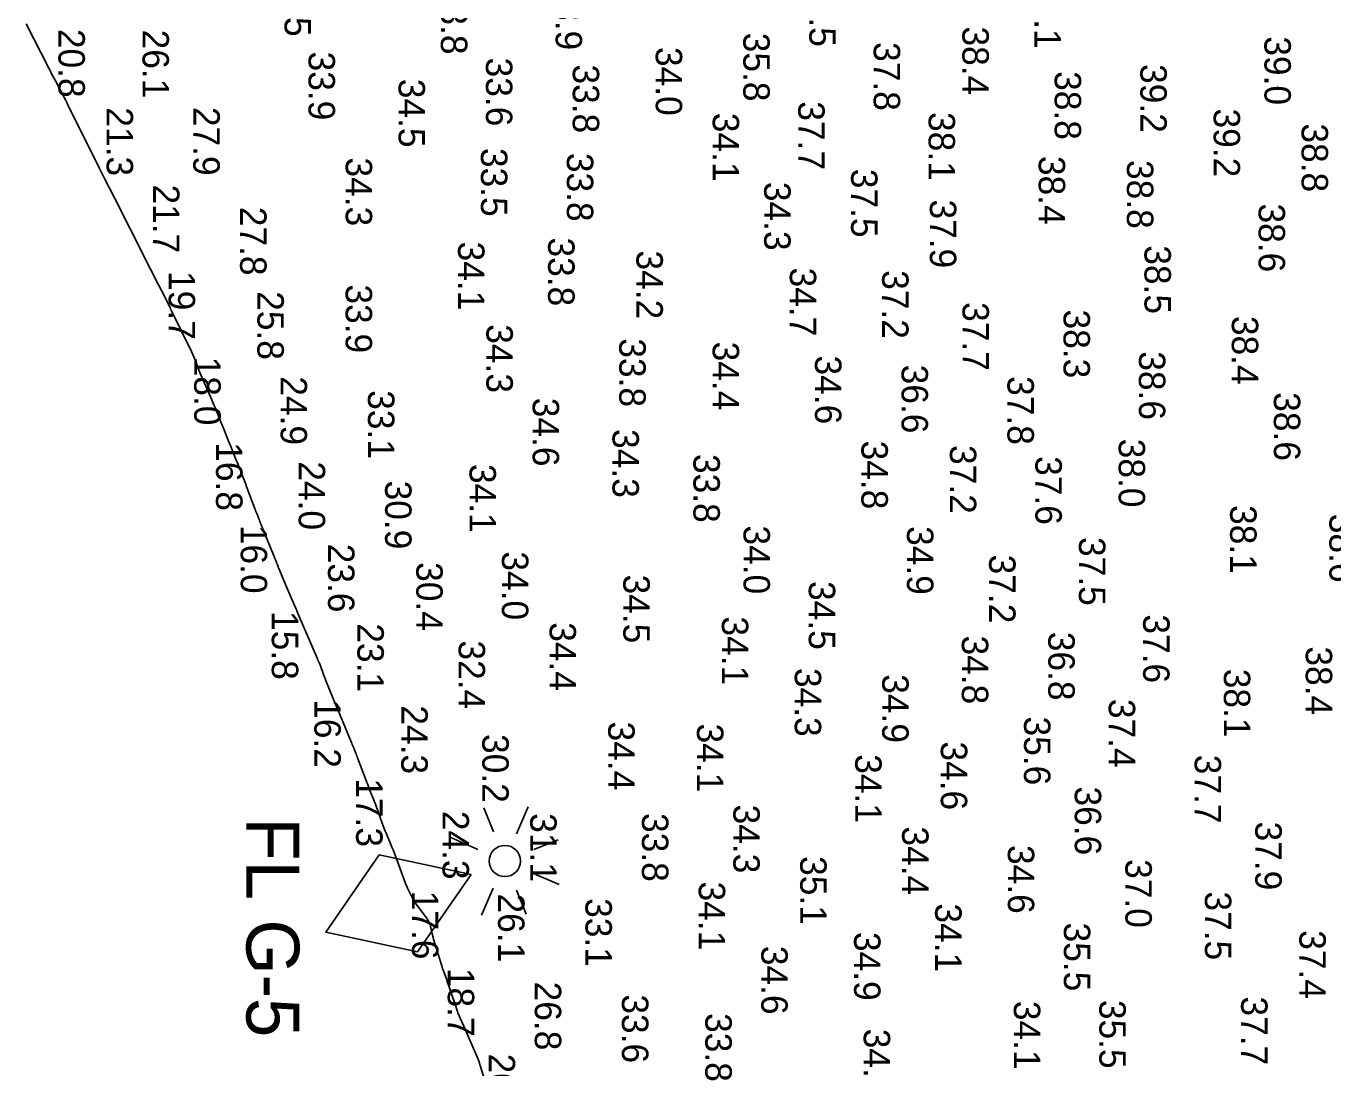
# Model space of a CAD drawing. Extents: x 1178573 to 1187098, y 693282 to 751751.
# Drawn here: x 1180180 to 1180798, y 702455 to 702948 of the extents above; entities that cross this region are included whole.
import ezdxf

# ---------------------------------------------------------------- set-up
doc = ezdxf.new("R2010")
doc.units = 0
for name, color, linetype in [('V-CHAN-NAID', 7, 'Continuous'), ('V-HYDS-MINR', 7, 'Continuous'), ('V-HYDS-SOUN', 7, 'Continuous'), ('V-HYDS-SOUN-EXSS', 7, 'Continuous')]:
    doc.layers.add(name, color=color, linetype=linetype)

msp = doc.modelspace()

# ---------------------------------------------------------------- linework, layer by layer
at = {"layer": 'V-CHAN-NAID'}
for p, q in [((1180417.09, 702578.21), (1180411.56, 702565.41)), ((1180400.58, 702566.35), (1180396.03, 702577.81)), ((1180393.24, 702558.13), (1180380.44, 702563.66)), ((1180419.78, 702558.07), (1180431.24, 702562.62)), ((1180431.64, 702541.56), (1180418.84, 702547.09)), ((1180400.52, 702539.81), (1180394.99, 702527.01)), ((1180411.5, 702538.87), (1180416.05, 702527.41))]:
    msp.add_line(p, q, dxfattribs=at)
msp.add_lwpolyline([(1180390.01, 702546.24), (1180346.55, 702555.5), (1180321.29, 702518.95), (1180364.75, 702509.69)], close=True, dxfattribs=at)
msp.add_circle((1180406.04, 702552.61), 7.39, dxfattribs=at)
at = {"layer": 'V-HYDS-MINR'}
msp.add_lwpolyline([(1180179.5, 702948.68), (1180190.18, 702927.76), (1180190.96, 702926.24), (1180191.74, 702924.73), (1180192.53, 702923.22), (1180193.32, 702921.72), (1180196.51, 702915.7), (1180197.31, 702914.19), (1180198.09, 702912.68), (1180198.86, 702911.16), (1180199.62, 702909.64), (1180211.96, 702884.85), (1180214.27, 702880.21), (1180216.6, 702875.58), (1180218.93, 702870.95), (1180221.26, 702866.32), (1180236.11, 702837.02), (1180236.66, 702835.94), (1180237.21, 702834.86), (1180237.76, 702833.77), (1180238.3, 702832.69), (1180241.11, 702827.09), (1180241.34, 702826.64), (1180241.58, 702826.18), (1180241.82, 702825.72), (1180242.07, 702825.27), (1180243.06, 702823.47), (1180243.31, 702823.02), (1180243.55, 702822.56), (1180243.79, 702822.1), (1180244.02, 702821.65), (1180245.75, 702818.24), (1180245.95, 702817.85), (1180246.15, 702817.46), (1180246.34, 702817.07), (1180246.54, 702816.68), (1180247.56, 702814.63), (1180247.63, 702814.48), (1180247.7, 702814.34), (1180247.76, 702814.19), (1180247.82, 702814.04), (1180248.04, 702813.44), (1180248.09, 702813.29), (1180248.15, 702813.14), (1180248.22, 702813), (1180248.29, 702812.85), (1180257.7, 702793.72), (1180258.21, 702792.64), (1180258.7, 702791.54), (1180259.16, 702790.43), (1180259.59, 702789.31), (1180261.27, 702784.81), (1180261.69, 702783.69), (1180262.14, 702782.57), (1180262.6, 702781.46), (1180263.08, 702780.36), (1180266.86, 702771.91), (1180267.38, 702770.73), (1180267.89, 702769.55), (1180268.38, 702768.36), (1180268.87, 702767.17), (1180270.84, 702762.25), (1180271.29, 702761.12), (1180271.75, 702759.99), (1180272.2, 702758.87), (1180272.66, 702757.74), (1180274.49, 702753.23), (1180274.95, 702752.1), (1180275.41, 702750.97), (1180275.87, 702749.85), (1180276.33, 702748.72), (1180278.94, 702742.32), (1180279.36, 702741.29), (1180279.77, 702740.26), (1180280.18, 702739.22), (1180280.59, 702738.18), (1180282.2, 702734.03), (1180282.61, 702733), (1180283.01, 702731.96), (1180283.4, 702730.92), (1180283.8, 702729.87), (1180287.78, 702719.29), (1180288.02, 702718.65), (1180288.26, 702718.01), (1180288.5, 702717.38), (1180288.74, 702716.74), (1180289.7, 702714.18), (1180289.94, 702713.55), (1180290.19, 702712.91), (1180290.44, 702712.28), (1180290.69, 702711.64), (1180298.09, 702693.48), (1180298.17, 702693.28), (1180298.25, 702693.07), (1180298.33, 702692.87), (1180298.41, 702692.66), (1180298.71, 702691.85), (1180298.78, 702691.64), (1180298.86, 702691.44), (1180298.94, 702691.23), (1180299.02, 702691.03), (1180302.65, 702682.32), (1180303.11, 702681.22), (1180303.58, 702680.12), (1180304.06, 702679.03), (1180304.55, 702677.94), (1180307.31, 702671.79), (1180307.4, 702671.6), (1180307.48, 702671.4), (1180307.56, 702671.21), (1180307.64, 702671.01), (1180307.94, 702670.22), (1180308.02, 702670.02), (1180308.1, 702669.83), (1180308.18, 702669.63), (1180308.26, 702669.43), (1180317.33, 702648.25), (1180317.43, 702648.02), (1180317.54, 702647.79), (1180317.64, 702647.56), (1180317.75, 702647.33), (1180318.19, 702646.41), (1180318.3, 702646.18), (1180318.4, 702645.94), (1180318.49, 702645.71), (1180318.58, 702645.47), (1180320.17, 702640.92), (1180320.47, 702640.08), (1180320.78, 702639.25), (1180321.1, 702638.42), (1180321.42, 702637.59), (1180325.98, 702626.35), (1180326.13, 702625.98), (1180326.29, 702625.61), (1180326.45, 702625.25), (1180326.61, 702624.89), (1180327.27, 702623.44), (1180327.43, 702623.08), (1180327.59, 702622.72), (1180327.75, 702622.35), (1180327.9, 702621.99), (1180333.32, 702608.93), (1180333.57, 702608.31), (1180333.83, 702607.7), (1180334.08, 702607.08), (1180334.34, 702606.46), (1180335.36, 702603.99), (1180335.61, 702603.37), (1180335.86, 702602.75), (1180336.1, 702602.13), (1180336.34, 702601.5), (1180340.37, 702590.71), (1180340.74, 702589.73), (1180341.11, 702588.75), (1180341.49, 702587.78), (1180341.88, 702586.8), (1180343.44, 702582.91), (1180343.83, 702581.94), (1180344.21, 702580.96), (1180344.57, 702579.97), (1180344.93, 702578.99), (1180347.95, 702570.51), (1180348.41, 702569.23), (1180348.9, 702567.96), (1180349.4, 702566.69), (1180349.93, 702565.43), (1180352.06, 702560.4), (1180352.58, 702559.14), (1180353.09, 702557.88), (1180353.59, 702556.61), (1180354.07, 702555.33), (1180358.83, 702542.43), (1180359.18, 702541.52), (1180359.56, 702540.63), (1180359.95, 702539.74), (1180360.38, 702538.87), (1180362.13, 702535.4), (1180362.58, 702534.54), (1180363.07, 702533.71), (1180363.6, 702532.89), (1180364.16, 702532.1), (1180369.2, 702525.29), (1180369.77, 702524.44), (1180370.24, 702523.53), (1180370.61, 702522.59), (1180370.89, 702521.6), (1180371.81, 702517.55), (1180372.05, 702516.54), (1180372.31, 702515.53), (1180372.58, 702514.53), (1180372.88, 702513.54), (1180376.02, 702503.45), (1180376.29, 702502.61), (1180376.56, 702501.78), (1180376.84, 702500.96), (1180377.14, 702500.13), (1180378.33, 702496.84), (1180378.63, 702496.02), (1180378.92, 702495.19), (1180379.21, 702494.37), (1180379.49, 702493.54), (1180383.61, 702481.33), (1180383.78, 702480.83), (1180383.97, 702480.34), (1180384.16, 702479.85), (1180384.37, 702479.36), (1180385.24, 702477.43), (1180385.45, 702476.95), (1180385.66, 702476.46), (1180385.88, 702475.98), (1180386.09, 702475.5), (1180393.26, 702459.18), (1180393.37, 702458.92), (1180393.47, 702458.65), (1180393.56, 702458.38), (1180393.65, 702458.11), (1180393.98, 702457.01), (1180394.06, 702456.74), (1180394.14, 702456.46), (1180394.22, 702456.19), (1180394.31, 702455.91), (1180398.97, 702440.99)], dxfattribs=at)

# ---------------------------------------------------------------- texts
at = {"layer": 'V-CHAN-NAID'}
msp.add_text('FL G-5', height=25, rotation=270, dxfattribs=at).set_placement((1180283.71, 702573.24))
at = {"layer": 'V-HYDS-SOUN'}
for s, p in [('33.5 ', (1180301.78, 702975.16)), ('33.9 ', (1180430.03, 702968.75)), ('37.5 ', (1180550.04, 702970.34)), ('39.1 ', (1180656.57, 702969.46)), ('33.8 ', (1180375.73, 702966.71)), ('20.8 ', (1180194.79, 702946.31)), ('26.1 ', (1180234.56, 702945.97)), ('35.8 ', (1180518.84, 702944.5)), ('38.4 ', (1180622.47, 702947.47)), ('34.0 ', (1180477.39, 702937.75)), ('37.8 ', (1180580.52, 702940.07)), ('39.0 ', (1180765.38, 702942.81)), ('33.9 ', (1180313.13, 702935.58)), ('33.6 ', (1180397.04, 702932.72)), ('33.8 ', (1180438.13, 702929.48)), ('38.8 ', (1180666.15, 702926.33)), ('39.2 ', (1180706.68, 702929.67)), ('34.5 ', (1180355.72, 702922.7)), ('21.3 ', (1180217.58, 702909.2)), ('27.9 ', (1180258.6, 702909.4)), ('34.1 ', (1180504.34, 702906.6)), ('37.7 ', (1180544.81, 702912.06)), ('38.1 ', (1180606.5, 702906.96)), ('39.2 ', (1180741.36, 702908.64)), ('38.8 ', (1180782.98, 702901.59)), ('33.5 ', (1180394.69, 702889.99)), ('34.3 ', (1180330.71, 702885.48)), ('33.8 ', (1180435.34, 702887.65)), ('38.4 ', (1180658.59, 702886.21)), ('38.8 ', (1180700.33, 702884.27)), ('37.5 ', (1180569.82, 702880.11)), ('21.7 ', (1180239.53, 702872.69)), ('34.3 ', (1180528.7, 702873.93)), ('37.9 ', (1180607.09, 702865.6)), ('38.6 ', (1180762.63, 702863.7)), ('27.8 ', (1180280.75, 702862.15)), ('34.1 ', (1180383.87, 702845.68)), ('33.8 ', (1180426.48, 702847.62)), ('34.2 ', (1180468.26, 702841.48)), ('38.5 ', (1180708.63, 702843.93)), ('34.7 ', (1180540.81, 702833.38)), ('37.2 ', (1180584.5, 702832.16)), ('19.7 ', (1180246.95, 702831.74)), ('25.8 ', (1180288.92, 702822.23)), ('33.9 ', (1180330.68, 702825.41)), ('37.7 ', (1180622.54, 702817.04)), ('38.3 ', (1180670.34, 702813.53)), ('38.4 ', (1180749.96, 702810.52)), ('34.3 ', (1180397.27, 702806.58)), ('33.8 ', (1180460.14, 702799.92)), ('34.4 ', (1180504.33, 702798.35)), ('18.0 ', (1180259.05, 702791.23)), ('34.6 ', (1180552.75, 702791.78)), ('38.6 ', (1180706, 702793.78)), ('36.6 ', (1180593.7, 702787.45)), ('24.9 ', (1180299.91, 702781.94)), ('37.8 ', (1180643.8, 702782.04)), ('33.1 ', (1180341.25, 702775.37)), ('34.6 ', (1180419.16, 702771.8)), ('38.6 ', (1180769.84, 702774.42)), ('34.3 ', (1180456.92, 702756.97)), ('38.0 ', (1180696.42, 702752.42)), ('16.8 ', (1180269.36, 702750.74)), ('34.8 ', (1180574.71, 702751.52)), ('37.2 ', (1180616.55, 702749.42)), ('24.0 ', (1180308.46, 702741.72)), ('34.1 ', (1180389.28, 702740.46)), ('33.8 ', (1180495.22, 702745.19)), ('37.6 ', (1180657.02, 702744.18)), ('30.9 ', (1180349.35, 702732.59)), ('38.1 ', (1180749.16, 702721.01)), ('38.6 ', (1180796.12, 702716.88)), ('16.0 ', (1180281.03, 702711.67)), ('34.0 ', (1180518.93, 702711.38)), ('34.9 ', (1180596.27, 702711.07)), ('23.6 ', (1180322.34, 702702.74)), ('37.5 ', (1180677.63, 702705.9)), ('34.0 ', (1180404.62, 702699.11)), ('37.2 ', (1180635.12, 702697.58)), ('30.4 ', (1180364.1, 702694.02)), ('34.5 ', (1180462.05, 702688.15)), ('34.5 ', (1180549.81, 702685.07)), ('15.8 ', (1180295.74, 702670.88)), ('34.4 ', (1180427.16, 702665.58)), ('34.1 ', (1180508.67, 702668.35)), ('37.6 ', (1180708, 702669.31)), ('23.1 ', (1180336.23, 702665.07)), ('34.8 ', (1180622.22, 702659.3)), ('36.8 ', (1180663.13, 702661.07)), ('32.4 ', (1180384.12, 702656.98)), ('38.4 ', (1180784.94, 702654.16)), ('34.3 ', (1180543.17, 702643.95)), ('34.9 ', (1180584.55, 702640.99)), ('38.1 ', (1180746.2, 702643.58)), ('16.2 ', (1180315.87, 702629.18)), ('37.4 ', (1180691.73, 702629.32)), ('24.3 ', (1180357.02, 702626.26)), ('34.4 ', (1180454.92, 702618.59)), ('34.1 ', (1180496.89, 702617.66)), ('35.6 ', (1180651.64, 702620.98)), ('30.2 ', (1180395.33, 702612.68)), ('34.6 ', (1180612.27, 702609.2)), ('34.1 ', (1180571.76, 702603.12)), ('37.7 ', (1180732.38, 702602.9)), ('17.3 ', (1180335.63, 702591.75)), ('36.6 ', (1180675.65, 702587.88)), ('34.3 ', (1180514.1, 702579.31)), ('33.8 ', (1180470.87, 702575.31)), ('34.4 ', (1180593.96, 702568.99)), ('37.9 ', (1180761.06, 702571.28)), ('34.6 ', (1180643.99, 702560.19)), ('35.1 ', (1180545.74, 702554.93)), ('37.0 ', (1180699.6, 702553.5)), ('34.1 ', (1180497.74, 702542.89)), ('37.5 ', (1180737.21, 702538.22)), ('33.1 ', (1180444.14, 702535.05)), ('34.1 ', (1180609.59, 702532.55)), ('35.5 ', (1180670.51, 702523.49)), ('34.9 ', (1180571.23, 702519.04)), ('37.4 ', (1180781.92, 702519.88)), ('34.6 ', (1180527.33, 702512.48)), ('18.7 ', (1180379, 702502.05)), ('26.8 ', (1180420.18, 702495.55)), ('33.6 ', (1180461.41, 702489.52)), ('34.1 ', (1180646.83, 702486.46)), ('35.5 ', (1180687.28, 702486.91)), ('37.7 ', (1180754.36, 702488.53)), ('33.8 ', (1180500.86, 702480.66)), ('34.1 ', (1180575.8, 702473.27)), ('20.1 ', (1180398.34, 702461.49))]:
    msp.add_text(s, height=12.5, rotation=270, dxfattribs=at).set_placement(p)
at = {"layer": 'V-HYDS-SOUN-EXSS'}
for s, p in [('24.3 ', (1180376.51, 702576.36)), ('31.1 ', (1180418.02, 702575.24)), ('17.6 ', (1180362.04, 702538.57)), ('26.1 ', (1180402.8, 702537.25))]:
    msp.add_text(s, height=12.5, rotation=270, dxfattribs=at).set_placement(p)

doc.saveas('drawing.dxf')
